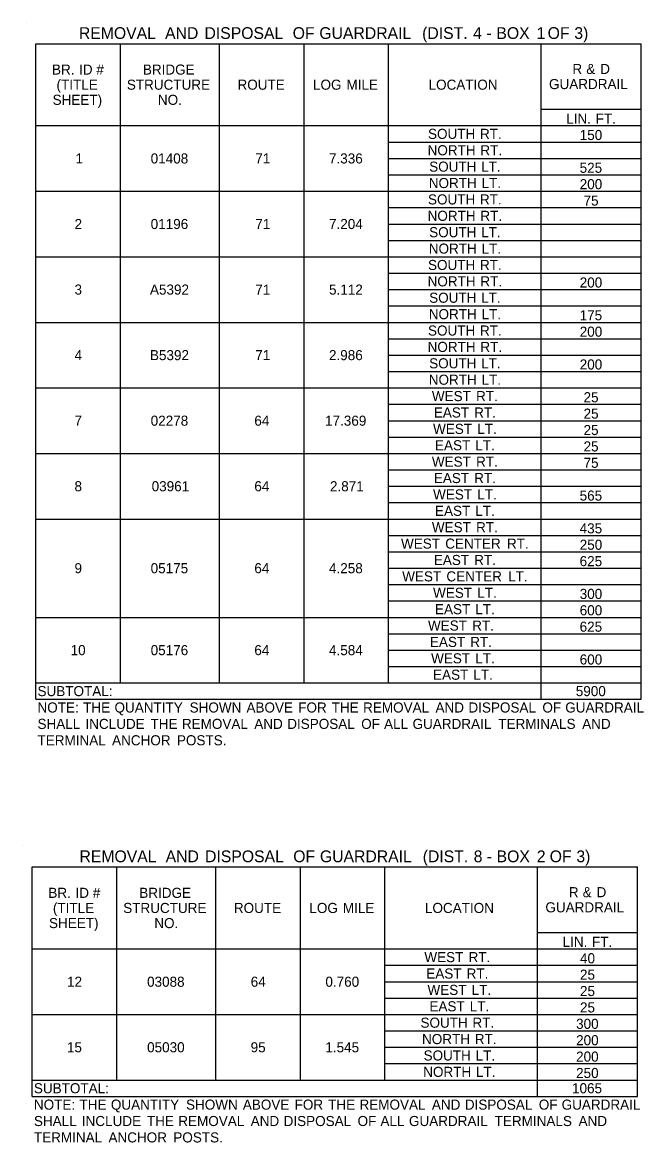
# Model space of a CAD drawing. Extents: x 540541 to 1930787, y -1948574 to 596640.
# Drawn here: x 546357 to 546727, y -1946823 to -1946156 of the extents above; entities that cross this region are included whole.
import ezdxf

# ---------------------------------------------------------------- set-up
doc = ezdxf.new("R2010")
doc.units = 0
doc.layers.add('Default', color=7, linetype='Continuous')
doc.layers.add('R_Border', color=7, linetype='Continuous')

msp = doc.modelspace()

# ---------------------------------------------------------------- linework, layer by layer
at = {"layer": 'Default'}
for p, q in [((546365.46, -1946168.99), (546725.23, -1946168.99)), ((546365.46, -1946558.99), (546365.46, -1946168.99)), ((546365.46, -1946558.99), (546365.46, -1946168.99)), ((546415.67, -1946549.24), (546415.67, -1946168.99)), ((546474.66, -1946549.24), (546474.66, -1946168.99)), ((546524.87, -1946549.24), (546524.87, -1946168.99)), ((546575.08, -1946549.24), (546575.08, -1946168.99)), ((546665.76, -1946558.99), (546665.76, -1946168.99)), ((546725.23, -1946558.99), (546725.23, -1946168.99)), ((546665.76, -1946207.99), (546725.23, -1946207.99)), ((546365.46, -1946217.74), (546725.23, -1946217.74)), ((546365.46, -1946217.74), (546725.23, -1946217.74)), ((546575.08, -1946227.49), (546725.23, -1946227.49)), ((546575.08, -1946237.24), (546725.23, -1946237.24)), ((546575.08, -1946246.99), (546725.23, -1946246.99)), ((546365.46, -1946256.74), (546725.23, -1946256.74)), ((546575.08, -1946266.49), (546725.23, -1946266.49)), ((546575.08, -1946276.24), (546725.23, -1946276.24)), ((546575.08, -1946285.99), (546725.23, -1946285.99)), ((546365.46, -1946295.74), (546725.23, -1946295.74)), ((546575.08, -1946305.49), (546725.23, -1946305.49)), ((546575.08, -1946315.24), (546725.23, -1946315.24)), ((546575.08, -1946324.99), (546725.23, -1946324.99)), ((546365.46, -1946334.74), (546725.23, -1946334.74)), ((546575.08, -1946344.49), (546725.23, -1946344.49)), ((546575.08, -1946354.24), (546725.23, -1946354.24)), ((546575.08, -1946363.99), (546725.23, -1946363.99)), ((546365.46, -1946373.74), (546725.23, -1946373.74)), ((546575.08, -1946383.49), (546725.23, -1946383.49)), ((546575.08, -1946393.24), (546725.23, -1946393.24)), ((546575.08, -1946402.99), (546725.23, -1946402.99)), ((546365.46, -1946412.74), (546725.23, -1946412.74)), ((546575.08, -1946422.49), (546725.23, -1946422.49)), ((546575.08, -1946432.24), (546725.23, -1946432.24)), ((546575.08, -1946441.99), (546725.23, -1946441.99)), ((546365.46, -1946451.74), (546725.23, -1946451.74)), ((546575.08, -1946461.49), (546725.23, -1946461.49)), ((546575.08, -1946471.24), (546725.23, -1946471.24)), ((546575.08, -1946480.99), (546725.23, -1946480.99)), ((546575.08, -1946490.74), (546725.23, -1946490.74)), ((546575.08, -1946500.49), (546725.23, -1946500.49)), ((546365.46, -1946510.24), (546725.23, -1946510.24)), ((546575.08, -1946519.99), (546725.23, -1946519.99)), ((546575.08, -1946529.74), (546725.23, -1946529.74)), ((546575.08, -1946539.49), (546725.23, -1946539.49)), ((546365.46, -1946549.24), (546725.23, -1946549.24)), ((546365.46, -1946549.24), (546725.23, -1946549.24)), ((546365.46, -1946558.99), (546725.23, -1946558.99)), ((546363.31, -1946658.74), (546723.09, -1946658.74)), ((546363.31, -1946795.24), (546363.31, -1946658.74)), ((546363.31, -1946795.24), (546363.31, -1946658.74)), ((546413.52, -1946785.49), (546413.52, -1946658.74)), ((546472.51, -1946785.49), (546472.51, -1946658.74)), ((546522.72, -1946785.49), (546522.72, -1946658.74)), ((546572.94, -1946785.49), (546572.94, -1946658.74)), ((546663.61, -1946795.24), (546663.61, -1946658.74)), ((546723.09, -1946795.24), (546723.09, -1946658.74)), ((546663.61, -1946697.74), (546723.09, -1946697.74)), ((546363.31, -1946707.49), (546723.09, -1946707.49)), ((546363.31, -1946707.49), (546663.61, -1946707.49)), ((546572.94, -1946717.24), (546723.09, -1946717.24)), ((546572.94, -1946726.99), (546723.09, -1946726.99)), ((546572.94, -1946736.74), (546723.09, -1946736.74)), ((546363.31, -1946746.49), (546723.09, -1946746.49)), ((546572.94, -1946756.24), (546723.09, -1946756.24)), ((546572.94, -1946765.99), (546723.09, -1946765.99)), ((546572.94, -1946775.74), (546723.09, -1946775.74)), ((546363.31, -1946785.49), (546723.09, -1946785.49)), ((546363.31, -1946785.49), (546723.09, -1946785.49)), ((546363.31, -1946795.24), (546723.09, -1946795.24))]:
    msp.add_line(p, q, dxfattribs=at)
at = {"layer": 'R_Border'}
for p, q in [((546359.61, -1946156.31), (546359.61, -1946156.31)), ((546357.46, -1946646.06), (546357.46, -1946646.06))]:
    msp.add_line(p, q, dxfattribs=at)

# ---------------------------------------------------------------- texts
at = {"layer": 'Default'}
for s, height, p in [('REMOVAL', 7, (546391.04, -1946166.15)), (' DISPOSAL', 7, (546463.08, -1946166.15)), (' OF', 7, (546515.51, -1946166.15)), (' GUARDRAIL', 7, (546531.35, -1946166.15)), (' (DIST.', 7, (546592.46, -1946166.15)), (' BOX', 7, (546636.58, -1946166.15)), (' OF', 7, (546667.05, -1946166.15)), (' 3)', 7, (546682.9, -1946166.15)), (' AND', 7, (546439.66, -1946166.15)), (' 4', 7, (546622.75, -1946166.15)), (' -', 7, (546630.68, -1946166.15)), (' 1', 7, (546660.48, -1946166.15)), ('BR.', 6, (546375.04, -1946187.36)), (' ID', 6, (546388.9, -1946187.36)), (' #', 6, (546399.2, -1946187.36)), ('BRIDGE', 6, (546429.07, -1946187.36)), ('R', 6, (546684.38, -1946186.99)), (' &', 6, (546690.4, -1946186.99)), (' D', 6, (546698.64, -1946186.99)), ('(TITLE', 6, (546377.73, -1946196.36)), ('STRUCTURE', 6, (546419.52, -1946196.36)), ('ROUTE', 6, (546485.3, -1946196.36)), ('LOG', 6, (546530.18, -1946196.36)), (' MILE', 6, (546547.84, -1946196.36)), ('LOCATION', 6, (546598.87, -1946196.36)), ('GUARDRAIL', 6, (546670.47, -1946195.99)), ('SHEET)', 6, (546375.41, -1946205.36)), ('NO.', 6, (546438, -1946205.36)), ('LIN.', 6, (546680.71, -1946216.54)), (' FT.', 6, (546695.96, -1946216.54)), ('SOUTH', 6, (546598.54, -1946225.61)), (' RT.', 6, (546627.2, -1946225.61)), ('150', 6, (546688.71, -1946226.29)), ('NORTH', 6, (546598.3, -1946235.36)), (' RT.', 6, (546627.44, -1946235.36)), ('1', 6, (546389, -1946240.24)), ('01408', 6, (546433.7, -1946240.24)), ('71', 6, (546495.87, -1946240.24)), ('7.336', 6, (546539.68, -1946240.24)), ('SOUTH', 6, (546599.23, -1946245.11)), (' LT.', 6, (546627.9, -1946245.11)), ('525', 6, (546688.67, -1946245.79)), ('NORTH', 6, (546599, -1946254.86)), (' LT.', 6, (546628.13, -1946254.86)), ('200', 6, (546688.71, -1946255.54)), ('SOUTH', 6, (546598.54, -1946264.61)), (' RT.', 6, (546627.2, -1946264.61)), ('75', 6, (546691, -1946265.29)), ('NORTH', 6, (546598.3, -1946274.36)), (' RT.', 6, (546627.44, -1946274.36)), ('2', 6, (546388.46, -1946279.24)), ('01196', 6, (546433.7, -1946279.24)), ('71', 6, (546495.87, -1946279.24)), ('7.204', 6, (546539.7, -1946279.24)), ('SOUTH', 6, (546599.23, -1946284.11)), (' LT.', 6, (546627.9, -1946284.11)), ('NORTH', 6, (546599, -1946293.86)), (' LT.', 6, (546628.13, -1946293.86)), ('SOUTH', 6, (546598.54, -1946303.61)), (' RT.', 6, (546627.2, -1946303.61)), ('3', 6, (546388.42, -1946318.24)), ('A5392', 6, (546433.27, -1946318.24)), ('71', 6, (546495.87, -1946318.24)), ('5.112', 6, (546539.71, -1946318.24)), ('NORTH', 6, (546598.3, -1946313.36)), (' RT.', 6, (546627.44, -1946313.36)), ('200', 6, (546688.71, -1946314.04)), ('SOUTH', 6, (546599.23, -1946323.11)), (' LT.', 6, (546627.9, -1946323.11)), ('NORTH', 6, (546599, -1946332.86)), (' LT.', 6, (546628.13, -1946332.86)), ('175', 6, (546688.67, -1946333.54)), ('SOUTH', 6, (546598.54, -1946342.61)), (' RT.', 6, (546627.2, -1946342.61)), ('200', 6, (546688.71, -1946343.29)), ('4', 6, (546388.44, -1946357.24)), ('B5392', 6, (546433.27, -1946357.24)), ('71', 6, (546495.87, -1946357.24)), ('2.986', 6, (546539.68, -1946357.24)), ('NORTH', 6, (546598.3, -1946352.36)), (' RT.', 6, (546627.44, -1946352.36)), ('SOUTH', 6, (546599.23, -1946362.11)), (' LT.', 6, (546627.9, -1946362.11)), ('200', 6, (546688.71, -1946362.79)), ('NORTH', 6, (546599, -1946371.86)), (' LT.', 6, (546628.13, -1946371.86)), ('WEST', 6, (546600.84, -1946381.61)), (' RT.', 6, (546624.89, -1946381.61)), ('25', 6, (546691, -1946382.29)), ('EAST', 6, (546602, -1946391.36)), (' RT.', 6, (546623.74, -1946391.36)), ('7', 6, (546388.42, -1946396.24)), ('02278', 6, (546433.7, -1946396.24)), ('64', 6, (546495.31, -1946396.24)), ('17.369', 6, (546537.35, -1946396.24)), ('25', 6, (546691, -1946392.04)), ('WEST', 6, (546601.54, -1946401.11)), (' LT.', 6, (546625.59, -1946401.11)), ('25', 6, (546691, -1946401.79)), ('EAST', 6, (546602.7, -1946410.86)), (' LT.', 6, (546624.43, -1946410.86)), ('25', 6, (546691, -1946411.54)), ('WEST', 6, (546600.84, -1946420.61)), (' RT.', 6, (546624.89, -1946420.61)), ('75', 6, (546691, -1946421.29)), ('EAST', 6, (546602, -1946430.36)), (' RT.', 6, (546623.74, -1946430.36)), ('8', 6, (546388.42, -1946435.24)), ('03961', 6, (546434.28, -1946435.24)), ('64', 6, (546495.31, -1946435.24)), ('2.871', 6, (546540.26, -1946435.24)), ('WEST', 6, (546601.54, -1946440.11)), (' LT.', 6, (546625.59, -1946440.11)), ('565', 6, (546688.67, -1946440.79)), ('EAST', 6, (546602.7, -1946449.86)), (' LT.', 6, (546624.43, -1946449.86)), ('WEST', 6, (546600.84, -1946459.61)), (' RT.', 6, (546624.89, -1946459.61)), ('435', 6, (546688.67, -1946460.29)), ('WEST', 6, (546582.5, -1946469.36)), (' CENTER', 6, (546606.55, -1946469.36)), (' RT.', 6, (546643.24, -1946469.36)), ('250', 6, (546688.71, -1946470.04)), ('9', 6, (546388.42, -1946483.99)), ('05175', 6, (546433.68, -1946483.99)), ('64', 6, (546495.31, -1946483.99)), ('4.258', 6, (546539.68, -1946483.99)), ('EAST', 6, (546602, -1946479.11)), (' RT.', 6, (546623.74, -1946479.11)), ('625', 6, (546688.67, -1946479.79)), ('WEST', 6, (546583.2, -1946488.86)), (' CENTER', 6, (546607.25, -1946488.86)), (' LT.', 6, (546643.94, -1946488.86)), ('WEST', 6, (546601.54, -1946498.61)), (' LT.', 6, (546625.59, -1946498.61)), ('300', 6, (546688.71, -1946499.29)), ('EAST', 6, (546602.7, -1946508.36)), (' LT.', 6, (546624.43, -1946508.36)), ('600', 6, (546688.71, -1946509.04)), ('WEST', 6, (546598.52, -1946518.11)), (' RT.', 6, (546622.57, -1946518.11)), ('625', 6, (546688.67, -1946518.79)), ('EAST', 6, (546599.68, -1946527.86)), (' RT.', 6, (546621.41, -1946527.86)), ('10', 6, (546386.1, -1946532.74)), ('05176', 6, (546433.7, -1946532.74)), ('64', 6, (546495.31, -1946532.74)), ('4.584', 6, (546539.7, -1946532.74)), ('WEST', 6, (546600.38, -1946537.61)), (' LT.', 6, (546624.43, -1946537.61)), ('600', 6, (546688.71, -1946538.29)), ('EAST', 6, (546601.54, -1946547.36)), (' LT.', 6, (546623.27, -1946547.36)), ('SUBTOTAL:', 6, (546366.43, -1946557.11)), ('5900', 6, (546686.38, -1946557.11)), ('NOTE:', 6, (546366.43, -1946566.86)), (' THE', 6, (546391.32, -1946566.86)), (' QUANTITY', 6, (546409.97, -1946566.86)), (' SHOWN', 6, (546454.62, -1946566.86)), (' ABOVE', 6, (546488.4, -1946566.86)), (' FOR', 6, (546519.17, -1946566.86)), (' THE', 6, (546539.08, -1946566.86)), (' REMOVAL', 6, (546557.73, -1946566.86)), (' AND', 6, (546600.76, -1946566.86)), (' DISPOSAL', 6, (546620.34, -1946566.86)), (' OF', 6, (546664.31, -1946566.86)), (' GUARDRAIL', 6, (546677.9, -1946566.86)), ('SHALL', 6, (546366.43, -1946576.61)), (' INCLUDE', 6, (546392.7, -1946576.61)), (' THE', 6, (546431.38, -1946576.61)), (' REMOVAL', 6, (546450.03, -1946576.61)), (' AND', 6, (546493.05, -1946576.61)), (' DISPOSAL', 6, (546512.64, -1946576.61)), (' OF', 6, (546556.6, -1946576.61)), (' ALL', 6, (546570.19, -1946576.61)), (' GUARDRAIL', 6, (546587.13, -1946576.61)), (' TERMINALS', 6, (546638.08, -1946576.61)), (' AND', 6, (546687.95, -1946576.61)), ('TERMINAL', 6, (546366.43, -1946586.36)), (' ANCHOR', 6, (546408.52, -1946586.36)), (' POSTS.', 6, (546447.07, -1946586.36)), ('REMOVAL', 7, (546391.38, -1946655.9)), (' AND', 7, (546440, -1946655.9)), (' DISPOSAL', 7, (546463.42, -1946655.9)), (' OF', 7, (546515.84, -1946655.9)), (' GUARDRAIL', 7, (546531.69, -1946655.9)), (' (DIST.', 7, (546592.8, -1946655.9)), (' 8', 7, (546623.09, -1946655.9)), (' BOX', 7, (546636.71, -1946655.9)), (' 2', 7, (546660.61, -1946655.9)), (' OF', 7, (546668.27, -1946655.9)), (' 3)', 7, (546684.12, -1946655.9)), (' -', 7, (546630.81, -1946655.9)), ('BR.', 6, (546372.89, -1946677.11)), (' ID', 6, (546386.76, -1946677.11)), (' #', 6, (546397.05, -1946677.11)), ('BRIDGE', 6, (546426.92, -1946677.11)), ('R', 6, (546682.24, -1946676.74)), (' &', 6, (546688.25, -1946676.74)), (' D', 6, (546696.5, -1946676.74)), ('(TITLE', 6, (546375.59, -1946686.11)), ('STRUCTURE', 6, (546417.37, -1946686.11)), ('ROUTE', 6, (546483.15, -1946686.11)), ('LOG', 6, (546528.03, -1946686.11)), (' MILE', 6, (546545.69, -1946686.11)), ('LOCATION', 6, (546596.72, -1946686.11)), ('GUARDRAIL', 6, (546668.32, -1946685.74)), ('SHEET)', 6, (546373.26, -1946695.11)), ('NO.', 6, (546435.85, -1946695.11)), ('LIN.', 6, (546678.56, -1946706.29)), (' FT.', 6, (546693.82, -1946706.29)), ('WEST', 6, (546596.37, -1946715.36)), (' RT.', 6, (546620.42, -1946715.36)), ('40', 6, (546688.89, -1946716.04)), ('12', 6, (546383.98, -1946729.99)), ('03088', 6, (546431.55, -1946729.99)), ('64', 6, (546493.16, -1946729.99)), ('0.760', 6, (546537.55, -1946729.99)), ('EAST', 6, (546597.53, -1946725.11)), (' RT.', 6, (546619.26, -1946725.11)), ('25', 6, (546688.86, -1946725.79)), ('WEST', 6, (546598.23, -1946734.86)), (' LT.', 6, (546622.28, -1946734.86)), ('25', 6, (546688.86, -1946735.54)), ('EAST', 6, (546599.39, -1946744.61)), (' LT.', 6, (546621.12, -1946744.61)), ('25', 6, (546688.86, -1946745.29)), ('SOUTH', 6, (546594.06, -1946754.36)), (' RT.', 6, (546622.73, -1946754.36)), ('300', 6, (546686.56, -1946755.04)), ('NORTH', 6, (546594.99, -1946764.11)), (' RT.', 6, (546624.13, -1946764.11)), ('200', 6, (546686.56, -1946764.79)), ('15', 6, (546383.92, -1946768.99)), ('05030', 6, (546431.57, -1946768.99)), ('95', 6, (546493.12, -1946768.99)), ('1.545', 6, (546537.51, -1946768.99)), ('SOUTH', 6, (546595.92, -1946773.86)), (' LT.', 6, (546624.59, -1946773.86)), ('200', 6, (546686.56, -1946774.54)), ('NORTH', 6, (546595.69, -1946783.61)), (' LT.', 6, (546624.82, -1946783.61)), ('250', 6, (546686.56, -1946784.29)), ('SUBTOTAL:', 6, (546364.29, -1946793.36)), ('1065', 6, (546684.15, -1946793.36)), ('NOTE:', 6, (546364.29, -1946803.11)), (' THE', 6, (546389.17, -1946803.11)), (' QUANTITY', 6, (546407.82, -1946803.11)), (' SHOWN', 6, (546452.48, -1946803.11)), (' ABOVE', 6, (546486.25, -1946803.11)), (' FOR', 6, (546517.03, -1946803.11)), (' THE', 6, (546536.94, -1946803.11)), (' REMOVAL', 6, (546555.59, -1946803.11)), (' AND', 6, (546598.62, -1946803.11)), (' DISPOSAL', 6, (546618.2, -1946803.11)), (' OF', 6, (546662.16, -1946803.11)), (' GUARDRAIL', 6, (546675.75, -1946803.11)), ('SHALL', 6, (546364.29, -1946812.86)), (' INCLUDE', 6, (546390.55, -1946812.86)), (' THE', 6, (546429.23, -1946812.86)), (' REMOVAL', 6, (546447.88, -1946812.86)), (' AND', 6, (546490.91, -1946812.86)), (' DISPOSAL', 6, (546510.49, -1946812.86)), (' OF', 6, (546554.46, -1946812.86)), (' ALL', 6, (546568.04, -1946812.86)), (' GUARDRAIL', 6, (546584.99, -1946812.86)), (' TERMINALS', 6, (546635.93, -1946812.86)), (' AND', 6, (546685.8, -1946812.86)), ('TERMINAL', 6, (546364.29, -1946822.61)), (' ANCHOR', 6, (546406.38, -1946822.61)), (' POSTS.', 6, (546444.93, -1946822.61))]:
    msp.add_text(s, height=height, dxfattribs=at).set_placement(p)

doc.saveas('drawing.dxf')
